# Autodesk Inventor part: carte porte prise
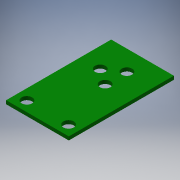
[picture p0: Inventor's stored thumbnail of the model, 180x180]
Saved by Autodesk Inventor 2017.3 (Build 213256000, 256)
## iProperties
Part Number: carte porte prise
Material: Générique
Document SubType Name: Modeling
Designer: ficho
Density: 1 g/cm^3
Appearance: Vert foncé
Author: ficho
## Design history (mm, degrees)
sketch "Esquisse1"
  geometry: L1 (-5.68, 19.2)-(12.22, 19.2); L2 (12.22, 19.2)-(12.22, -10.8); L3 (12.22, -10.8)-(-5.68, -10.8); L4 (-5.68, -10.8)-(-5.68, 19.2); C1 r 1.5 at (4.5, 13.5); C2 r 1.5 at (-0.25, 10.65); C3 r 1.5 at (4.5, 7.3); C4 r 1.5 at (-2.68, -7.87); C5 r 1.5 at (9.22, -7.87); C6 r 0.9 at (-4.4, 17.97) reference; C7 r 0.9 at (10.84, 17.97) reference; 2 further points
  constraints: 8 end point, 5 centre point, 2 parallel, 1 horizontal, 1 perpendicular
  dimensions: "d0" = 3 diameter of C1; "d1" = 3 diameter of C2; "d2" = 3 diameter of C3; "d3" = 3 diameter of C4; "d4" = 3 diameter of C5; "d5" = 3 distance from line of L4 C4.centre; "d6" = 3 distance from line of C5.centre L2; "d7" = 17.9 distance between parallel lines of L2 L4; "d8" = 30 distance between parallel lines of L1 L3; "d9" = 19.2 distance from line of L1 point (0, 0); "d12" = 12.2196 distance from line of L2 point (0, 0); "d13" = 5.7 distance from line of C1.centre L1; "d14" = 6.2 distance of C3.centre C1.centre; "d15" = 4.75 horizontal distance of C2.centre C1.centre; "d16" = 8.55 distance from line of C2.centre L1; "d17" = 5.4304 distance from line of L4 C2.centre
extrude "Extrusion1" new body sketch "Esquisse1" distance "d10" = 1; taper "d11" = 0 deg
node "Solide1"
node "Référence1"
node "Référence2"
